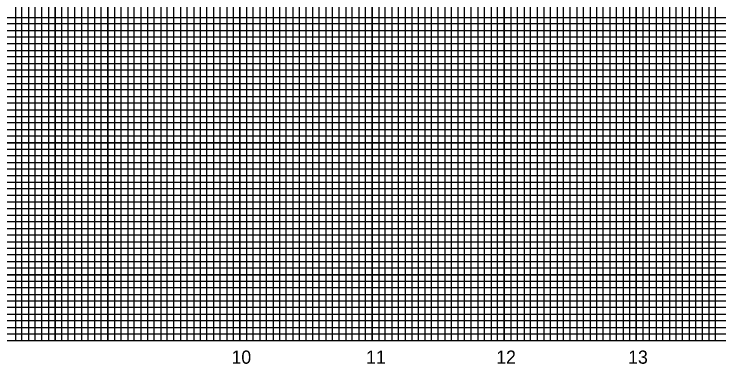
# Model space of a CAD drawing. Extents: x 2180324 to 2182216, y 74532 to 75632.
# Drawn here: x 2181270 to 2181803, y 75090 to 75355 of the extents above; entities that cross this region are included whole.
import ezdxf

# ---------------------------------------------------------------- set-up
doc = ezdxf.new("R2010")
doc.units = 0
for name, color, linetype in [('Exist Structure Minor Culvert Topo', 7, 'Continuous'), ('Old_Level_1', 7, 'Continuous'), ('Old_Level_11', 7, 'Continuous'), ('Old_Level_2', 7, 'Continuous'), ('Sheet Cutting Line CELL', 7, 'Continuous'), ('Sheet Plot Border Inside CELL', 7, 'Continuous'), ('Sheet Plot Border Outside CELL', 7, 'Continuous'), ('Sheet Sticker Exception Certification CELL', 7, 'Continuous')]:
    doc.layers.add(name, color=color, linetype=linetype)

msp = doc.modelspace()

# ---------------------------------------------------------------- linework, layer by layer
at = {"layer": 'Exist Structure Minor Culvert Topo'}
msp.add_lwpolyline([(2181300.9, 75607.28), (2181300.9, 75107.28), (2181940.9, 75107.28), (2181940.9, 75446.23), (2181790.85, 75446.23), (2181790.85, 75607.28)], close=True, dxfattribs=at)
at = {"layer": 'Old_Level_11'}
for p, q in [((2181290.9, 75107.28), (2181290.9, 75607.28)), ((2181340.9, 75107.28), (2181340.9, 75607.28)), ((2181390.9, 75107.28), (2181390.9, 75607.28)), ((2181440.9, 75107.28), (2181440.9, 75607.28)), ((2181490.9, 75107.28), (2181490.9, 75607.28)), ((2181540.9, 75107.28), (2181540.9, 75607.28)), ((2181590.9, 75107.28), (2181590.9, 75607.28)), ((2181640.9, 75107.28), (2181640.9, 75607.28)), ((2181690.9, 75107.28), (2181690.9, 75607.28)), ((2181740.9, 75107.28), (2181740.9, 75607.28)), ((2181790.9, 75107.28), (2181790.9, 75469.73)), ((2181990.9, 75307.28), (2180490.9, 75307.28)), ((2181990.9, 75257.28), (2180490.9, 75257.28)), ((2181990.9, 75207.28), (2180490.9, 75207.28)), ((2181990.9, 75157.28), (2180490.9, 75157.28))]:
    msp.add_line(p, q, dxfattribs=at)
at = {"layer": 'Old_Level_2'}
for points in [[(2181265.9, 75107.28), (2181315.9, 75107.28), (2181315.9, 75607.28), (2181365.9, 75607.28), (2181365.9, 75107.28), (2181415.9, 75107.28), (2181415.9, 75607.28), (2181465.9, 75607.28), (2181465.9, 75107.28), (2181515.9, 75107.28), (2181515.9, 75607.28), (2181565.9, 75607.28), (2181565.9, 75107.28), (2181615.9, 75107.28), (2181615.9, 75607.28), (2181665.9, 75607.28), (2181665.9, 75107.28), (2181715.9, 75107.28), (2181715.9, 75607.28), (2181765.9, 75607.28), (2181765.9, 75107.28), (2181815.9, 75107.28), (2181815.9, 75446.23)], [(2181990.9, 75332.28), (2180490.9, 75332.28), (2180490.9, 75282.28), (2181990.9, 75282.28)], [(2181990.9, 75232.28), (2180490.9, 75232.28), (2180490.9, 75182.28), (2181990.9, 75182.28)], [(2181990.9, 75132.28), (2180490.9, 75132.28)]]:
    msp.add_lwpolyline(points, dxfattribs=at)
at = {"layer": 'Sheet Cutting Line CELL'}
msp.add_line((2180490.9, 75107.28), (2181990.9, 75107.28), dxfattribs=at)
at = {"layer": 'Sheet Plot Border Inside CELL'}
msp.add_lwpolyline([(2180540.9, 75446.23), (2180540.9, 75107.28), (2181940.9, 75107.28), (2181940.9, 75446.23)], dxfattribs=at)
at = {"layer": 'Sheet Plot Border Outside CELL'}
for p, q in [((2180540.9, 75352.28), (2181940.9, 75352.28)), ((2181940.9, 75347.28), (2180540.9, 75347.28)), ((2180540.9, 75342.28), (2181940.9, 75342.28)), ((2181940.9, 75337.28), (2180540.9, 75337.28)), ((2180540.9, 75327.28), (2181940.9, 75327.28)), ((2181940.9, 75322.28), (2180540.9, 75322.28)), ((2180540.9, 75317.28), (2181940.9, 75317.28)), ((2181940.9, 75312.28), (2180540.9, 75312.28)), ((2180540.9, 75302.28), (2181940.9, 75302.28)), ((2181940.9, 75297.28), (2180540.9, 75297.28)), ((2180540.9, 75292.28), (2181940.9, 75292.28)), ((2181940.9, 75287.28), (2180540.9, 75287.28)), ((2180540.9, 75277.28), (2181940.9, 75277.28)), ((2181940.9, 75272.28), (2180540.9, 75272.28)), ((2180540.9, 75267.28), (2181940.9, 75267.28)), ((2181940.9, 75262.28), (2180540.9, 75262.28)), ((2180540.9, 75252.28), (2181940.9, 75252.28)), ((2181940.9, 75247.28), (2180540.9, 75247.28)), ((2180540.9, 75242.28), (2181940.9, 75242.28)), ((2181940.9, 75237.28), (2180540.9, 75237.28)), ((2180540.9, 75227.28), (2181940.9, 75227.28)), ((2181940.9, 75222.28), (2180540.9, 75222.28)), ((2181940.9, 75217.28), (2180540.9, 75217.28)), ((2181940.9, 75212.28), (2180540.9, 75212.28)), ((2180540.9, 75202.28), (2181940.9, 75202.28)), ((2181940.9, 75197.28), (2180540.9, 75197.28)), ((2180540.9, 75192.28), (2181940.9, 75192.28)), ((2181940.9, 75187.28), (2180540.9, 75187.28)), ((2180540.9, 75177.28), (2181940.9, 75177.28)), ((2181940.9, 75172.28), (2180540.9, 75172.28)), ((2180540.9, 75167.28), (2181940.9, 75167.28)), ((2181940.9, 75162.28), (2180540.9, 75162.28)), ((2180540.9, 75152.28), (2181940.9, 75152.28)), ((2181940.9, 75147.28), (2180540.9, 75147.28)), ((2180540.9, 75142.28), (2181940.9, 75142.28)), ((2181940.9, 75137.28), (2180540.9, 75137.28)), ((2180540.9, 75127.28), (2181940.9, 75127.28)), ((2181940.9, 75122.28), (2180540.9, 75122.28)), ((2180540.9, 75117.28), (2181940.9, 75117.28))]:
    msp.add_line(p, q, dxfattribs=at)
for points in [[(2181270.9, 75607.28), (2181270.9, 75107.28), (2181275.9, 75107.28), (2181275.9, 75607.28)], [(2181280.9, 75607.28), (2181280.9, 75107.28), (2181285.9, 75107.28), (2181285.9, 75607.28)], [(2181295.9, 75607.28), (2181295.9, 75107.28), (2181300.9, 75107.28), (2181300.9, 75607.28)], [(2181305.9, 75607.28), (2181305.9, 75107.28), (2181310.9, 75107.28), (2181310.9, 75607.28)], [(2181320.9, 75607.28), (2181320.9, 75107.28), (2181325.9, 75107.28), (2181325.9, 75607.28)], [(2181330.9, 75607.28), (2181330.9, 75107.28), (2181335.9, 75107.28), (2181335.9, 75607.28)], [(2181345.9, 75607.28), (2181345.9, 75107.28), (2181350.9, 75107.28), (2181350.9, 75607.28)], [(2181355.9, 75607.28), (2181355.9, 75107.28), (2181360.9, 75107.28), (2181360.9, 75607.28)], [(2181370.9, 75607.28), (2181370.9, 75107.28), (2181375.9, 75107.28)], [(2181375.9, 75107.28), (2181375.9, 75607.28)], [(2181380.9, 75607.28), (2181380.9, 75107.28), (2181385.9, 75107.28), (2181385.9, 75607.28)], [(2181395.9, 75607.28), (2181395.9, 75107.28), (2181400.9, 75107.28), (2181400.9, 75607.28)], [(2181405.9, 75607.28), (2181405.9, 75107.28), (2181410.9, 75107.28), (2181410.9, 75607.28)], [(2181420.9, 75607.28), (2181420.9, 75107.28), (2181425.9, 75107.28), (2181425.9, 75607.28)], [(2181430.9, 75607.28), (2181430.9, 75107.28), (2181435.9, 75107.28), (2181435.9, 75607.28)], [(2181445.9, 75607.28), (2181445.9, 75107.28), (2181450.9, 75107.28), (2181450.9, 75607.28)], [(2181455.9, 75607.28), (2181455.9, 75107.28), (2181460.9, 75107.28), (2181460.9, 75607.28)], [(2181470.9, 75607.28), (2181470.9, 75107.28), (2181475.9, 75107.28), (2181475.9, 75607.28)], [(2181480.9, 75607.28), (2181480.9, 75107.28), (2181485.9, 75107.28), (2181485.9, 75607.28)], [(2181495.9, 75607.28), (2181495.9, 75107.28), (2181500.9, 75107.28), (2181500.9, 75607.28)], [(2181505.9, 75607.28), (2181505.9, 75107.28), (2181510.9, 75107.28), (2181510.9, 75607.28)], [(2181520.9, 75607.28), (2181520.9, 75107.28), (2181525.9, 75107.28), (2181525.9, 75607.28)], [(2181530.9, 75607.28), (2181530.9, 75107.28), (2181535.9, 75107.28), (2181535.9, 75607.28)], [(2181545.9, 75607.28), (2181545.9, 75107.28), (2181550.9, 75107.28), (2181550.9, 75607.28)], [(2181555.9, 75607.28), (2181555.9, 75107.28), (2181560.9, 75107.28), (2181560.9, 75607.28)], [(2181570.9, 75607.28), (2181570.9, 75107.28), (2181575.9, 75107.28), (2181575.9, 75607.28)], [(2181580.9, 75607.28), (2181580.9, 75107.28), (2181585.9, 75107.28), (2181585.9, 75607.28)], [(2181595.9, 75607.28), (2181595.9, 75107.28), (2181600.9, 75107.28), (2181600.9, 75607.28)], [(2181605.9, 75607.28), (2181605.9, 75107.28), (2181610.9, 75107.28), (2181610.9, 75607.28)], [(2181620.9, 75607.28), (2181620.9, 75107.28), (2181625.9, 75107.28), (2181625.9, 75607.28)], [(2181630.9, 75607.28), (2181630.9, 75107.28), (2181635.9, 75107.28), (2181635.9, 75607.28)], [(2181645.9, 75607.28), (2181645.9, 75107.28), (2181650.9, 75107.28), (2181650.9, 75607.28)], [(2181655.9, 75607.28), (2181655.9, 75107.28), (2181660.9, 75107.28), (2181660.9, 75607.28)], [(2181670.9, 75607.28), (2181670.9, 75107.28), (2181675.9, 75107.28), (2181675.9, 75607.28)], [(2181680.9, 75607.28), (2181680.9, 75107.28)], [(2181680.9, 75107.28), (2181685.9, 75107.28), (2181685.9, 75607.28)], [(2181695.9, 75607.28), (2181695.9, 75107.28), (2181700.9, 75107.28), (2181700.9, 75607.28)], [(2181705.9, 75607.28), (2181705.9, 75107.28), (2181710.9, 75107.28), (2181710.9, 75607.28)], [(2181720.9, 75607.28), (2181720.9, 75107.28), (2181725.9, 75107.28), (2181725.9, 75607.28)], [(2181730.9, 75607.28), (2181730.9, 75107.28), (2181735.9, 75107.28), (2181735.9, 75607.28)], [(2181745.9, 75607.28), (2181745.9, 75107.28), (2181750.9, 75107.28), (2181750.9, 75607.28)], [(2181755.9, 75607.28), (2181755.9, 75107.28), (2181760.9, 75107.28), (2181760.9, 75607.28)], [(2181770.9, 75607.28), (2181770.9, 75107.28), (2181775.9, 75107.28), (2181775.9, 75607.28)], [(2181780.9, 75607.28), (2181780.9, 75107.28), (2181785.9, 75107.28), (2181785.9, 75607.28)], [(2181795.9, 75446.23), (2181795.9, 75107.28), (2181800.9, 75107.28), (2181800.9, 75446.23)], [(2181940.9, 75112.28), (2180540.9, 75112.28)]]:
    msp.add_lwpolyline(points, dxfattribs=at)
at = {"layer": 'Sheet Sticker Exception Certification CELL'}
for points in [[(2181240.9, 75107.28), (2181290.9, 75107.28), (2181290.9, 75607.28), (2181340.9, 75607.28), (2181340.9, 75107.28), (2181390.9, 75107.28), (2181390.9, 75607.28), (2181440.9, 75607.28), (2181440.9, 75107.28), (2181490.9, 75107.28), (2181490.9, 75607.28), (2181540.9, 75607.28), (2181540.9, 75107.28), (2181590.9, 75107.28), (2181590.9, 75607.28), (2181640.9, 75607.28), (2181640.9, 75107.28), (2181690.9, 75107.28), (2181690.9, 75607.28), (2181740.9, 75607.28), (2181740.9, 75107.28), (2181790.9, 75107.28), (2181790.9, 75607.28), (2181817.2, 75607.28)], [(2181990.9, 75307.28), (2180490.9, 75307.28), (2180490.9, 75257.28), (2181990.9, 75257.28)], [(2181990.9, 75207.28), (2180490.9, 75207.28), (2180490.9, 75207.28), (2180490.9, 75157.28), (2181990.9, 75157.28)]]:
    msp.add_lwpolyline(points, dxfattribs=at)

# ---------------------------------------------------------------- texts
at = {"layer": 'Old_Level_1'}
for s, p in [('10', (2181434.49, 75089.78)), ('11', (2181536.33, 75089.78)), ('12', (2181634.87, 75089.78)), ('13', (2181734.71, 75089.78))]:
    msp.add_text(s, height=10, dxfattribs=at).set_placement(p)

doc.saveas('drawing.dxf')
